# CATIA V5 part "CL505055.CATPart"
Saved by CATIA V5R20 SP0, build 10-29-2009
Part number: CL505055
Bounding box of the stored display mesh (mm): x -27.5 to 27.5, y -51 to 0, z -18 to 18
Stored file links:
  C:\Users\Raffaele\Desktop\3D X SITO CF\BOLEX\17-CENTERER REF 505\CL505055.CATPart
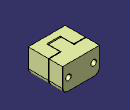
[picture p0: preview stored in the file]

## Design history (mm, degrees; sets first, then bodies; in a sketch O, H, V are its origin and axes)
Set1
  DatumSurface1 to DatumSurface183 "MANIFOLD_SOLID_BREP #4927"
  DatumSurface184 to DatumSurface212 "MANIFOLD_SOLID_BREP #5819"
Body1 (main body)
